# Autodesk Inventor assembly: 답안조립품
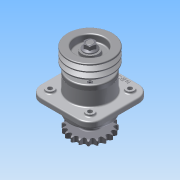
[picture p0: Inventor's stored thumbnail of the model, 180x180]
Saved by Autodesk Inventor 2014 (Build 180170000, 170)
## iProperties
Created: 2015-09
Part Number: 답안조립품
Document SubType Name: Assembly
Designer: study
Author: study
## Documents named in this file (12)
- C:\Users\study\Desktop\450909V1002\답안조립품.iam
- C:\Users\study\Desktop\450909V1002\1-본체.ipt
- C:\Users\study\Desktop\450909V1002\2-커버.ipt
- C:\Users\study\Desktop\450909V1002\3-축.ipt
- C:\Users\study\Desktop\450909V1002\4-V벨트풀리.ipt
- C:\Users\study\Desktop\450909V1002\5-체인 스프로킷.ipt
- C:\Users\study\Desktop\450909V1002\6-베어링 6206.ipt
- C:\Users\study\Desktop\450909V1002\7-부시.ipt
- C:\Users\study\Desktop\450909V1002\8-오일실 30x42.ipt
- C:\Users\study\Desktop\450909V1002\9-M16-너트.ipt
- C:\Users\study\Desktop\450909V1002\10-M6.ipt
- C:\Users\study\Desktop\450909V1002\11-키 6x6.ipt
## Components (23 placed, 11 different names)
1. 1-본체:1
2. 2-커버:1
3. 3-축:1 — 각도:1, 각도:2, 각도:5, 각도:6
4. 4-V벨트풀리:1 — 각도:3
5. 5-체인 스프로킷:1 — 각도:4
6. 6-베어링 6206:1
7. 7-부시:1
8. 8-8-오일실 30x42:1
9. 9-M16 너트:1 — 각도:6
10. 11-키 6x6:1 — 각도:1, 각도:3
11. 6-베어링 6206:2
12. 2-커버:2
13. 8-8-오일실 30x42:2
14. 11-키 6x6:2 — 각도:2, 각도:4
15. 9-M16 너트:2 — 각도:5
16. 10-M6:2
17. 10-M6:3
18. 10-M6:4
19. 10-M6:5
20. 10-M6:1
21. 10-M6:6
22. 10-M6:7
23. 10-M6:8
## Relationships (6: Angle 6)
- 각도:1 [Angle]: 3-축:1 ↔ 11-키 6x6:1
- 각도:2 [Angle]: 3-축:1 ↔ 11-키 6x6:2
- 각도:3 [Angle]: 4-V벨트풀리:1 ↔ 11-키 6x6:1
- 각도:4 [Angle]: 5-체인 스프로킷:1 ↔ 11-키 6x6:2
- 각도:5 [Angle]: 3-축:1 ↔ 9-M16 너트:2
- 각도:6 [Angle]: 3-축:1 ↔ 9-M16 너트:1
## Named parameters: d8_d6 = 0, d9_d7 = 0
